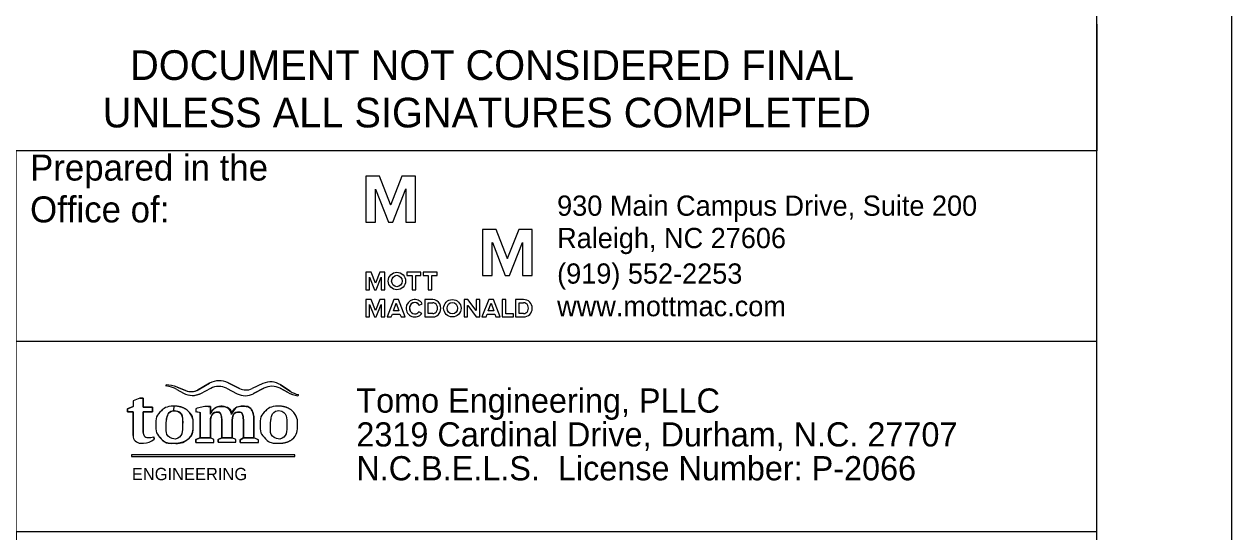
# Model space of a CAD drawing. Extents: x 2474053 to 2475957, y 620456 to 621556.
# Drawn here: x 2475529.3 to 2475752.9, y 621299.5 to 621393.6 of the extents above; entities that cross this region are included whole.
import ezdxf

# ---------------------------------------------------------------- set-up
doc = ezdxf.new("R2010")
doc.units = 0
for name, color, linetype in [('Old_Level_18', 7, 'Continuous'), ('Old_Level_2', 7, 'Continuous'), ('Old_Level_3', 7, 'Continuous'), ('Old_Level_40', 7, 'Continuous'), ('Old_Level_42', 7, 'Continuous'), ('Old_Level_43', 7, 'Continuous'), ('Old_Level_62', 7, 'Continuous'), ('Old_Level_63', 7, 'Continuous'), ('Sheet Sticker Exception Certification CELL', 7, 'Continuous')]:
    doc.layers.add(name, color=color, linetype=linetype)

msp = doc.modelspace()

# ---------------------------------------------------------------- linework, layer by layer
at = {"layer": 'Old_Level_18'}
msp.add_lwpolyline([(2475727.88, 621531.13), (2474227.88, 621531.13), (2474227.88, 620481.13), (2475727.88, 620481.13)], close=True, dxfattribs=at)
at = {"layer": 'Old_Level_2'}
for p, q in [((2475595.07, 621365.4), (2475592.54, 621365.4)), ((2475592.54, 621365.4), (2475592.54, 621356.9)), ((2475597.12, 621360.14), (2475595.07, 621365.4)), ((2475599.23, 621365.4), (2475597.17, 621360.14)), ((2475601.75, 621365.4), (2475599.23, 621365.4)), ((2475601.75, 621356.9), (2475601.75, 621365.4)), ((2475594.34, 621356.9), (2475594.34, 621363)), ((2475594.34, 621363), (2475594.36, 621363)), ((2475594.36, 621363), (2475596.76, 621356.9)), ((2475597.54, 621356.9), (2475599.93, 621363.03)), ((2475599.93, 621363.03), (2475599.95, 621363.03)), ((2475599.95, 621363.03), (2475599.95, 621356.9)), ((2475597.12, 621360.07), (2475597.12, 621360.14)), ((2475597.17, 621360.07), (2475597.12, 621360.07)), ((2475597.17, 621360.14), (2475597.17, 621360.07)), ((2475592.54, 621356.9), (2475594.34, 621356.9)), ((2475596.76, 621356.9), (2475597.54, 621356.9)), ((2475599.95, 621356.9), (2475601.75, 621356.9)), ((2475616.68, 621355.49), (2475614.16, 621355.49)), ((2475614.16, 621355.49), (2475614.16, 621346.99)), ((2475618.73, 621350.24), (2475616.68, 621355.49)), ((2475620.84, 621355.49), (2475618.79, 621350.24)), ((2475623.36, 621355.49), (2475620.84, 621355.49)), ((2475623.36, 621346.99), (2475623.36, 621355.49)), ((2475615.95, 621346.99), (2475615.95, 621353.1)), ((2475615.95, 621353.1), (2475615.98, 621353.1)), ((2475615.98, 621353.1), (2475618.37, 621346.99)), ((2475619.15, 621346.99), (2475621.54, 621353.13)), ((2475621.54, 621353.13), (2475621.57, 621353.13)), ((2475621.57, 621353.13), (2475621.57, 621346.99)), ((2475618.73, 621350.16), (2475618.73, 621350.24)), ((2475618.79, 621350.16), (2475618.73, 621350.16)), ((2475618.79, 621350.24), (2475618.79, 621350.16)), ((2475592.55, 621347.59), (2475592.54, 621344.34)), ((2475593.51, 621347.59), (2475592.55, 621347.59)), ((2475593.22, 621344.34), (2475593.22, 621346.68)), ((2475593.22, 621346.68), (2475593.25, 621346.68)), ((2475593.22, 621346.68), (2475593.25, 621346.68)), ((2475593.25, 621346.68), (2475594.16, 621344.34)), ((2475594.31, 621345.56), (2475593.51, 621347.59)), ((2475595.12, 621347.59), (2475594.31, 621345.56)), ((2475594.47, 621344.34), (2475595.38, 621346.68)), ((2475596.08, 621347.59), (2475595.12, 621347.59)), ((2475595.38, 621346.68), (2475595.4, 621346.68)), ((2475595.38, 621346.68), (2475595.4, 621346.68)), ((2475595.38, 621346.68), (2475595.4, 621346.68)), ((2475595.4, 621346.68), (2475595.4, 621344.34)), ((2475596.08, 621344.34), (2475596.08, 621347.59)), ((2475596.08, 621344.34), (2475596.08, 621347.59)), ((2475614.16, 621346.99), (2475615.95, 621346.99)), ((2475618.37, 621346.99), (2475619.15, 621346.99)), ((2475621.57, 621346.99), (2475623.36, 621346.99)), ((2475592.54, 621344.34), (2475593.22, 621344.34)), ((2475594.16, 621344.34), (2475594.47, 621344.34)), ((2475595.4, 621344.34), (2475596.08, 621344.34)), ((2475592.55, 621342.55), (2475592.54, 621339.3)), ((2475593.51, 621342.55), (2475592.55, 621342.55)), ((2475593.22, 621339.3), (2475593.22, 621341.64)), ((2475593.22, 621341.64), (2475593.25, 621341.64)), ((2475593.25, 621341.64), (2475594.16, 621339.3)), ((2475594.31, 621340.52), (2475593.51, 621342.55)), ((2475595.12, 621342.55), (2475594.31, 621340.52)), ((2475594.47, 621339.3), (2475595.38, 621341.64)), ((2475596.08, 621342.55), (2475595.12, 621342.55)), ((2475595.38, 621341.64), (2475595.4, 621341.64)), ((2475595.4, 621341.64), (2475595.4, 621339.3)), ((2475596.08, 621339.3), (2475596.08, 621342.55)), ((2475602.42, 621341.49), (2475602.99, 621341.75)), ((2475602.42, 621341.49), (2475602.99, 621341.75)), ((2475604.92, 621342.54), (2475603.44, 621342.55)), ((2475603.44, 621342.55), (2475603.44, 621340.86)), ((2475604.11, 621339.92), (2475604.11, 621341.95)), ((2475604.11, 621341.95), (2475604.92, 621341.95)), ((2475620.25, 621342.55), (2475620.25, 621342.55)), ((2475621.74, 621342.55), (2475620.25, 621342.55)), ((2475620.25, 621342.55), (2475620.25, 621340.86)), ((2475620.93, 621339.92), (2475620.93, 621341.95)), ((2475620.93, 621341.95), (2475621.74, 621341.95)), ((2475621.74, 621341.92), (2475621.74, 621341.92)), ((2475592.54, 621339.3), (2475593.22, 621339.3)), ((2475594.16, 621339.3), (2475594.47, 621339.3)), ((2475595.4, 621339.3), (2475596.08, 621339.3)), ((2475602.91, 621339.97), (2475602.34, 621340.24)), ((2475602.91, 621339.97), (2475602.34, 621340.24)), ((2475603.44, 621340.86), (2475603.44, 621339.3)), ((2475603.44, 621339.3), (2475604.92, 621339.3)), ((2475604.92, 621339.92), (2475604.11, 621339.92)), ((2475620.25, 621340.86), (2475620.25, 621339.3)), ((2475620.25, 621339.3), (2475621.74, 621339.3)), ((2475621.74, 621339.92), (2475620.93, 621339.92))]:
    msp.add_line(p, q, dxfattribs=at)
for points in [[(2475600.16, 621346.99), (2475601.1, 621346.99), (2475601.1, 621344.34), (2475601.8, 621344.34), (2475601.8, 621346.99), (2475602.73, 621346.99), (2475602.73, 621347.59), (2475600.16, 621347.59), (2475600.16, 621346.99)], [(2475603.15, 621346.99), (2475604.09, 621346.99), (2475604.09, 621344.34), (2475604.79, 621344.34), (2475604.79, 621346.99), (2475605.72, 621346.99), (2475605.72, 621347.59), (2475603.15, 621347.59), (2475603.15, 621346.99)], [(2475596.47, 621339.3), (2475597.25, 621339.3), (2475597.46, 621339.84), (2475598.86, 621339.84), (2475599.07, 621339.3), (2475599.82, 621339.3), (2475598.58, 621342.55), (2475597.72, 621342.55), (2475596.47, 621339.3)], [(2475597.64, 621340.44), (2475598.16, 621341.85), (2475598.68, 621340.44), (2475597.64, 621340.44)], [(2475611.39, 621341.4), (2475611.42, 621341.4), (2475612.98, 621339.3), (2475613.63, 621339.3), (2475613.63, 621342.55), (2475612.95, 621342.55), (2475612.95, 621340.49), (2475611.42, 621342.55), (2475610.74, 621342.55), (2475610.74, 621339.3), (2475611.39, 621339.3), (2475611.39, 621341.4)], [(2475614.04, 621339.3), (2475614.82, 621339.3), (2475615.03, 621339.84), (2475616.43, 621339.84), (2475616.64, 621339.3), (2475617.4, 621339.3), (2475616.15, 621342.55), (2475615.29, 621342.55), (2475614.04, 621339.3)], [(2475615.21, 621340.44), (2475615.73, 621341.84), (2475616.25, 621340.44), (2475615.21, 621340.44)], [(2475619.87, 621339.3), (2475619.87, 621339.87), (2475618.46, 621339.87), (2475618.46, 621342.55), (2475617.79, 621342.55), (2475617.79, 621339.3), (2475619.87, 621339.3)], [(2475619.87, 621339.3), (2475619.87, 621339.87), (2475618.46, 621339.87), (2475618.46, 621342.55), (2475617.79, 621342.55), (2475617.79, 621339.3), (2475619.86, 621339.3), (2475619.87, 621339.87)]]:
    msp.add_lwpolyline(points, dxfattribs=at)
msp.add_arc((2475621.74, 621340.92), 1.62, 270, 90, dxfattribs=at)
for centre, major_axis, ratio in [((2475598.29, 621345.96), (0, 1.62), 0.993118), ((2475598.29, 621345.96), (0, 1.06), 0.916103), ((2475608.56, 621340.92), (0, 1.62), 0.993118), ((2475608.56, 621340.92), (0, 1.06), 0.916103)]:
    msp.add_ellipse(centre, major_axis=major_axis, ratio=ratio, dxfattribs=at)
for centre, major_axis, ratio, start_param, end_param in [((2475601.6, 621340.92), (0, 1.62), 0.993118, 5.246647, 10.366427), ((2475601.6, 621340.92), (0, 1.62), 0.993118, 5.246647, 10.366427), ((2475601.6, 621340.92), (0, 1.06), 0.916103, 5.276876, 9.424778), ((2475601.6, 621340.92), (0, 1.06), 0.916103, 5.276876, 10.296021), ((2475604.92, 621340.92), (0, -1.62), 0.930276, 0, 3.141593), ((2475604.92, 621340.93), (0, -1.01), 0.900832, 0, 3.141593), ((2475621.74, 621340.93), (0, -1.01), 0.900832, 0, 3.141593), ((2475601.6, 621340.92), (0, 1.06), 0.916103, 3.141593, 4.012835)]:
    msp.add_ellipse(centre, major_axis=major_axis, ratio=ratio, start_param=start_param, end_param=end_param, dxfattribs=at)
at = {"layer": 'Old_Level_3'}
for p, q in [((2475557.57, 621325.86), (2475558.77, 621325.19)), ((2475557.57, 621325.86), (2475558.77, 621325.19)), ((2475557.6, 621326.29), (2475559.16, 621325.67)), ((2475559.16, 621325.67), (2475557.6, 621326.29)), ((2475561.5, 621325.83), (2475563.6, 621327.02)), ((2475563.6, 621327.02), (2475561.5, 621325.83)), ((2475562.02, 621325.14), (2475563.82, 621326.08)), ((2475562.02, 621325.14), (2475563.82, 621326.08)), ((2475566.76, 621326.09), (2475568.72, 621325.08)), ((2475566.76, 621326.09), (2475568.72, 621325.08)), ((2475567.05, 621327.11), (2475569.16, 621326.05)), ((2475569.16, 621326.05), (2475567.05, 621327.11)), ((2475573.5, 621326.96), (2475571.47, 621326.02)), ((2475573.5, 621326.96), (2475571.47, 621326.02)), ((2475573.64, 621326.09), (2475571.75, 621325.09)), ((2475571.75, 621325.09), (2475573.64, 621326.09)), ((2475578.04, 621325.36), (2475576.68, 621326.09)), ((2475576.68, 621326.09), (2475578.04, 621325.36)), ((2475576.77, 621326.71), (2475578.56, 621325.54)), ((2475578.56, 621325.54), (2475576.77, 621326.71)), ((2475549.45, 621323.77), (2475549.45, 621322.73)), ((2475549.45, 621323.77), (2475549.45, 621322.73)), ((2475550.71, 621324.23), (2475551.34, 621324.23)), ((2475551.34, 621324.23), (2475550.71, 621324.23)), ((2475551.34, 621324.23), (2475551.34, 621322.6)), ((2475551.34, 621322.6), (2475551.34, 621324.23)), ((2475548.4, 621322.28), (2475549.45, 621322.73)), ((2475549.45, 621322.73), (2475548.4, 621322.28)), ((2475548.4, 621321.73), (2475548.4, 621322.28)), ((2475548.4, 621322.28), (2475548.4, 621321.73)), ((2475549.44, 621321.73), (2475548.4, 621321.73)), ((2475548.4, 621321.73), (2475549.44, 621321.73)), ((2475549.44, 621317.32), (2475549.44, 621321.73)), ((2475549.44, 621321.73), (2475549.44, 621317.32)), ((2475551.34, 621322.6), (2475553.04, 621322.6)), ((2475553.04, 621322.6), (2475551.34, 621322.6)), ((2475557.02, 621322.79), (2475556.93, 621321.94)), ((2475557.02, 621322.79), (2475557.02, 621322.79)), ((2475561.04, 621322.28), (2475561.04, 621321.76)), ((2475561.04, 621322.28), (2475561.04, 621321.76)), ((2475563.33, 621322.74), (2475563.77, 621322.74)), ((2475563.77, 621322.74), (2475563.33, 621322.74)), ((2475563.77, 621322.74), (2475563.77, 621321.28)), ((2475563.77, 621321.28), (2475563.77, 621322.74)), ((2475553.28, 621317.11), (2475553.36, 621316.66)), ((2475553.36, 621316.66), (2475553.28, 621317.11)), ((2475561.04, 621316.57), (2475561.87, 621316.89)), ((2475561.87, 621316.89), (2475561.04, 621316.57)), ((2475563.78, 621316.89), (2475561.87, 621316.89)), ((2475564.43, 621316.57), (2475563.78, 621316.89)), ((2475564.43, 621316.57), (2475563.78, 621316.89)), ((2475565.21, 621316.58), (2475565.86, 621316.91)), ((2475565.86, 621316.91), (2475565.21, 621316.58)), ((2475567.78, 621316.91), (2475565.86, 621316.91)), ((2475568.47, 621316.58), (2475567.78, 621316.91)), ((2475568.47, 621316.58), (2475567.78, 621316.91)), ((2475569.26, 621316.56), (2475569.88, 621316.89)), ((2475569.88, 621316.89), (2475569.26, 621316.56)), ((2475571.8, 621316.89), (2475569.88, 621316.89)), ((2475572.65, 621316.56), (2475571.8, 621316.89)), ((2475572.65, 621316.56), (2475571.8, 621316.89)), ((2475550.86, 621315.92), (2475551.4, 621315.93)), ((2475550.86, 621315.92), (2475551.4, 621315.93)), ((2475561.04, 621316.06), (2475561.04, 621316.57)), ((2475561.04, 621316.57), (2475561.04, 621316.57)), ((2475561.04, 621316.57), (2475561.04, 621316.06)), ((2475561.04, 621316.06), (2475564.43, 621316.06)), ((2475561.04, 621316.06), (2475564.43, 621316.06)), ((2475564.43, 621316.06), (2475564.43, 621316.57)), ((2475564.43, 621316.57), (2475564.43, 621316.57)), ((2475564.43, 621316.06), (2475564.43, 621316.57)), ((2475565.08, 621316.58), (2475565.08, 621316.58)), ((2475565.21, 621316.08), (2475565.21, 621316.58)), ((2475565.21, 621316.58), (2475565.21, 621316.08)), ((2475565.21, 621316.08), (2475568.47, 621316.08)), ((2475565.21, 621316.08), (2475568.47, 621316.08)), ((2475568.47, 621316.08), (2475568.47, 621316.58)), ((2475568.47, 621316.58), (2475568.47, 621316.58)), ((2475568.47, 621316.08), (2475568.47, 621316.58)), ((2475569.05, 621316.56), (2475569.05, 621316.56)), ((2475569.26, 621316.06), (2475569.26, 621316.56)), ((2475569.26, 621316.56), (2475569.26, 621316.06)), ((2475569.26, 621316.06), (2475572.65, 621316.06)), ((2475569.26, 621316.06), (2475572.65, 621316.06)), ((2475572.44, 621316.56), (2475572.44, 621316.56)), ((2475572.65, 621316.06), (2475572.65, 621316.56)), ((2475572.65, 621316.06), (2475572.65, 621316.56)), ((2475579.37, 621313.76), (2475549.17, 621313.75)), ((2475579.37, 621313.76), (2475549.17, 621313.75)), ((2475549.17, 621313.75), (2475549.17, 621313.47)), ((2475549.17, 621313.75), (2475549.17, 621313.47)), ((2475549.17, 621313.47), (2475579.37, 621313.47)), ((2475549.17, 621313.47), (2475579.37, 621313.47)), ((2475579.37, 621313.47), (2475579.37, 621313.76)), ((2475579.37, 621313.47), (2475579.37, 621313.76)), ((2475579.37, 621313.47), (2475579.37, 621313.47))]:
    msp.add_line(p, q, dxfattribs=at)
for points in [[(2475553.04, 621322.6), (2475553.04, 621321.73), (2475551.33, 621321.73), (2475551.33, 621317.92)], [(2475551.33, 621317.92), (2475551.33, 621321.73), (2475553.04, 621321.73), (2475553.04, 621322.6)], [(2475563.78, 621320.37), (2475563.78, 621316.89), (2475561.87, 621316.89), (2475561.87, 621321.63)], [(2475561.87, 621321.63), (2475561.87, 621316.89), (2475563.78, 621316.89), (2475563.78, 621320.37)], [(2475567.78, 621320.18), (2475567.78, 621316.91), (2475565.86, 621316.91), (2475565.86, 621319.89)], [(2475565.86, 621319.89), (2475565.86, 621316.91), (2475567.78, 621316.91), (2475567.78, 621320.18)], [(2475571.8, 621320.2), (2475571.8, 621316.89), (2475569.88, 621316.89), (2475569.88, 621319.85)], [(2475569.88, 621319.85), (2475569.88, 621316.89), (2475571.8, 621316.89), (2475571.8, 621320.2)]]:
    msp.add_lwpolyline(points, dxfattribs=at)
for centre, radius, start, end in [((2475555.56, 621326.62), 0.0758, 89.4701, 262.0204), ((2475555.56, 621326.62), 0.0758, 89.4701, 262.0204), ((2475554.74, 621320.81), 5.79, 60.7255, 82.0204), ((2475554.74, 621320.81), 5.79, 60.7255, 82.0204), ((2475555.5, 621321.06), 5.64, 68.211, 89.4701), ((2475555.5, 621321.06), 5.64, 68.211, 89.4701), ((2475560.16, 621328.18), 2.71, 248.211, 308.9356), ((2475560.16, 621328.18), 2.71, 248.211, 299.5442), ((2475565.41, 621323.83), 3.66, 63.4105, 119.5442), ((2475565.41, 621323.83), 3.66, 63.4105, 119.5442), ((2475565.3, 621323.25), 3.19, 62.7919, 117.5568), ((2475565.3, 621323.25), 3.19, 62.7919, 117.5568), ((2475570.35, 621328.44), 2.67, 243.4105, 294.8953), ((2475570.35, 621328.44), 2.67, 243.4105, 294.8953), ((2475574.92, 621323.9), 3.37, 56.5776, 114.8953), ((2475574.92, 621323.9), 3.37, 56.5776, 114.8953), ((2475575.16, 621323.23), 3.24, 61.9151, 117.8233), ((2475575.16, 621323.23), 3.24, 61.9151, 117.8233), ((2475552.1, 621318.38), 6.01, 103.443, 116.1707), ((2475552.1, 621318.38), 6.01, 103.443, 116.1707), ((2475560.44, 621328.17), 3.41, 240.7255, 299.8298), ((2475560.44, 621328.17), 3.41, 240.7255, 297.5568), ((2475570.22, 621327.98), 3.27, 242.7919, 297.8233), ((2475570.22, 621327.98), 3.27, 242.7919, 297.8233), ((2475580.98, 621330.86), 6.24, 241.9151, 260.5433), ((2475580.98, 621330.86), 6.24, 241.9151, 260.5433), ((2475581.01, 621329.25), 4.46, 236.5776, 256.8197), ((2475581.01, 621329.25), 4.46, 236.5776, 256.8197), ((2475579.97, 621324.81), 0.105, 260.5433, 76.8197), ((2475579.97, 621324.81), 0.105, 260.5433, 76.8197), ((2475563.7, 621315.02), 7.73, 92.7753, 110.1143), ((2475563.7, 621315.02), 7.73, 92.7753, 110.1143), ((2475567.48, 621359.85), 38.63, 260.395, 261.6509), ((2475567.48, 621359.85), 38.63, 260.395, 261.6509), ((2475550.84, 621317.32), 1.4, 180, 270.9178), ((2475550.84, 621317.32), 1.4, 180, 270.9178), ((2475552.43, 621317.92), 1.1, 180, 216.038), ((2475552.43, 621317.92), 1.1, 180, 214.5443), ((2475552.17, 621317.74), 0.784, 214.2431, 269.2019), ((2475552.17, 621317.74), 0.784, 214.2431, 269.2019), ((2475552.21, 621320.67), 3.71, 269.2019, 286.6975), ((2475552.21, 621320.67), 3.71, 269.2019, 286.6975), ((2475551.35, 621319.07), 3.14, 270.9178, 309.9754), ((2475551.35, 621319.07), 3.14, 270.9178, 309.9754)]:
    msp.add_arc(centre, radius, start, end, dxfattribs=at)
for points, degree in [([(2475557.02, 621322.79), (2475555.57, 621322.79), (2475554.6, 621321.84), (2475553.64, 621320.88), (2475553.64, 621319.31), (2475553.64, 621317.76), (2475554.58, 621316.79), (2475555.53, 621315.82), (2475557.02, 621315.92)], 3), ([(2475557.02, 621322.79), (2475558.43, 621322.79), (2475559.54, 621322), (2475560.61, 621320.97), (2475560.6, 621319.29), (2475560.58, 621317.42), (2475559.53, 621316.57), (2475558.39, 621315.82), (2475557.02, 621315.92), (2475555.53, 621315.82), (2475554.58, 621316.79), (2475553.64, 621317.76), (2475553.64, 621319.31), (2475553.64, 621320.88), (2475554.6, 621321.84), (2475555.57, 621322.79), (2475557.02, 621322.79)], 3), ([(2475557.28, 621316.68), (2475555.45, 621316.83), (2475555.6, 621319.33), (2475555.6, 621320.31), (2475555.81, 621320.93), (2475556.14, 621321.88), (2475557.15, 621321.97)], 3), ([(2475557.28, 621316.68), (2475558.65, 621316.95), (2475558.58, 621319.37), (2475558.7, 621321.68), (2475557.15, 621321.97), (2475556.14, 621321.88), (2475555.81, 621320.93), (2475555.6, 621320.31), (2475555.6, 621319.33), (2475555.45, 621316.83), (2475557.28, 621316.68)], 3), ([(2475559.54, 621322), (2475558.43, 621322.79), (2475557.02, 621322.79)], 2), ([(2475557.15, 621321.97), (2475558.7, 621321.68), (2475558.58, 621319.37), (2475558.65, 621316.95), (2475557.28, 621316.68)], 3), ([(2475559.53, 621316.57), (2475560.58, 621317.42), (2475560.6, 621319.29), (2475560.61, 621320.97), (2475559.54, 621322)], 3), ([(2475563.77, 621321.28), (2475564.32, 621322.71), (2475565.87, 621322.76), (2475567.4, 621322.65), (2475567.68, 621321.22), (2475568.31, 621322.75), (2475569.85, 621322.78), (2475571.03, 621322.74), (2475571.48, 621321.93), (2475571.81, 621321.28), (2475571.8, 621320.2)], 3), ([(2475565.87, 621322.76), (2475564.32, 621322.71), (2475563.77, 621321.28)], 2), ([(2475565.86, 621319.89), (2475565.88, 621320.72), (2475565.72, 621321.09), (2475565.64, 621321.69), (2475564.94, 621321.69), (2475563.99, 621321.55), (2475563.78, 621320.37)], 3), ([(2475563.78, 621320.37), (2475563.99, 621321.55), (2475564.94, 621321.69)], 2), ([(2475564.94, 621321.69), (2475565.64, 621321.69), (2475565.72, 621321.09)], 2), ([(2475567.68, 621321.22), (2475567.4, 621322.65), (2475565.87, 621322.76)], 2), ([(2475571.8, 621320.2), (2475571.81, 621321.28), (2475571.48, 621321.93), (2475571.03, 621322.74), (2475569.85, 621322.78), (2475568.31, 621322.75), (2475567.68, 621321.22)], 3), ([(2475569.88, 621319.85), (2475569.88, 621320.5), (2475569.81, 621320.82), (2475569.67, 621321.69), (2475568.95, 621321.68), (2475567.88, 621321.59), (2475567.78, 621320.18)], 3), ([(2475567.78, 621320.18), (2475567.88, 621321.59), (2475568.95, 621321.68), (2475569.67, 621321.69), (2475569.81, 621320.82), (2475569.88, 621320.5), (2475569.88, 621319.85)], 3), ([(2475576.33, 621322.79), (2475574.88, 621322.79), (2475573.92, 621321.84), (2475572.95, 621320.88), (2475572.95, 621319.31), (2475572.95, 621317.76), (2475573.9, 621316.79), (2475574.84, 621315.82), (2475576.33, 621315.92)], 3), ([(2475576.6, 621316.68), (2475574.76, 621316.83), (2475574.92, 621319.33), (2475574.92, 621320.31), (2475575.12, 621320.93), (2475575.45, 621321.88), (2475576.46, 621321.97)], 3), ([(2475578.85, 621322), (2475577.74, 621322.79), (2475576.33, 621322.79)], 2), ([(2475576.46, 621321.97), (2475578.01, 621321.68), (2475577.89, 621319.37), (2475577.96, 621316.95), (2475576.6, 621316.68)], 3), ([(2475578.85, 621316.57), (2475579.89, 621317.42), (2475579.92, 621319.29), (2475579.92, 621320.97), (2475578.85, 621322)], 3), ([(2475565.72, 621321.09), (2475565.88, 621320.72), (2475565.86, 621319.89)], 2), ([(2475557.02, 621315.92), (2475558.39, 621315.82), (2475559.53, 621316.57)], 2), ([(2475576.33, 621315.92), (2475577.71, 621315.82), (2475578.85, 621316.57)], 2)]:
    msp.add_open_spline(points, degree=degree, dxfattribs=at)
at = {"layer": 'Old_Level_40'}
msp.add_lwpolyline([(2475527.83, 621274.49), (2475727.88, 621274.49), (2475727.88, 621299.48), (2475527.83, 621299.48)], close=True, dxfattribs=at)
at = {"layer": 'Old_Level_42'}
msp.add_line((2475727.88, 621299.48), (2475527.83, 621299.48), dxfattribs=at)
msp.add_lwpolyline([(2475727.88, 621334.78), (2475527.83, 621334.78), (2475527.83, 621370.08)], dxfattribs=at)
at = {"layer": 'Old_Level_43'}
msp.add_lwpolyline([(2475727.88, 621299.48), (2475527.83, 621299.48), (2475527.83, 621334.78)], dxfattribs=at)
at = {"layer": 'Old_Level_62'}
msp.add_lwpolyline([(2474077.88, 620481.13), (2475727.88, 620481.13), (2475727.88, 621531.13), (2474077.88, 621531.13)], close=True, dxfattribs=at)
at = {"layer": 'Old_Level_63'}
msp.add_lwpolyline([(2474052.88, 620456.13), (2475752.88, 620456.13), (2475752.88, 621556.13), (2474052.88, 621556.13)], close=True, dxfattribs=at)
at = {"layer": 'Sheet Sticker Exception Certification CELL'}
for p, q in [((2475727.87, 621393.57), (2475727.87, 621370.07)), ((2475727.87, 621370.08), (2475527.83, 621370.08))]:
    msp.add_line(p, q, dxfattribs=at)

# ---------------------------------------------------------------- texts
at = {"layer": 'Old_Level_2'}
for s, height, p in [('Prepared in the ', 4.8186, (2475530.38, 621364.58)), ('Office of:', 4.819, (2475530.38, 621356.83))]:
    msp.add_text(s, height=height, dxfattribs=at).set_placement(p)
for s, p in [('930 Main Campus Drive, Suite 200', (2475627.96, 621358.06)), ('Raleigh, NC 27606', (2475627.96, 621352.06)), ('(919) 552-2253', (2475627.96, 621345.48)), ('www.mottmac.com', (2475627.96, 621339.44))]:
    msp.add_text(s, height=3.75, rotation=360, dxfattribs=at).set_placement(p)
at = {"layer": 'Old_Level_3'}
for s, height, rotation, p in [('Tomo Engineering, PLLC', 4.483, 0.0019, (2475590.79, 621321.57)), ('2319 Cardinal Drive, Durham, N.C. 27707', 4.483, 0.0004, (2475590.79, 621315.3)), ('N.C.B.E.L.S.  License Number: P-2066', 4.483, 0.0004, (2475590.79, 621309.03)), ('ENGINEERING', 2.2803, 0.0004, (2475549.22, 621309.06))]:
    msp.add_text(s, height=height, rotation=rotation, dxfattribs=at).set_placement(p)
at = {"layer": 'Sheet Sticker Exception Certification CELL'}
for s, p in [('DOCUMENT NOT CONSIDERED FINAL', (2475548.9, 621383.23)), ('UNLESS ALL SIGNATURES COMPLETED', (2475543.83, 621374.43))]:
    msp.add_text(s, height=5.5, dxfattribs=at).set_placement(p)

doc.saveas('drawing.dxf')
